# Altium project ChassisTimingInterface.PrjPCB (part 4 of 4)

## Sheet ChassisTimingInterface7.SchDoc: External Sync
size B; Author: M. Pirello; Organization: LIGO Laboratory; Address1: California Institute of Technology; Address2: Massachusetts Institute of Technology; Address3: National Science Foundation; Address4: Australia 2086; DocumentNumber: 8; SheetNumber: 8; SheetTotal: 12; Size: B
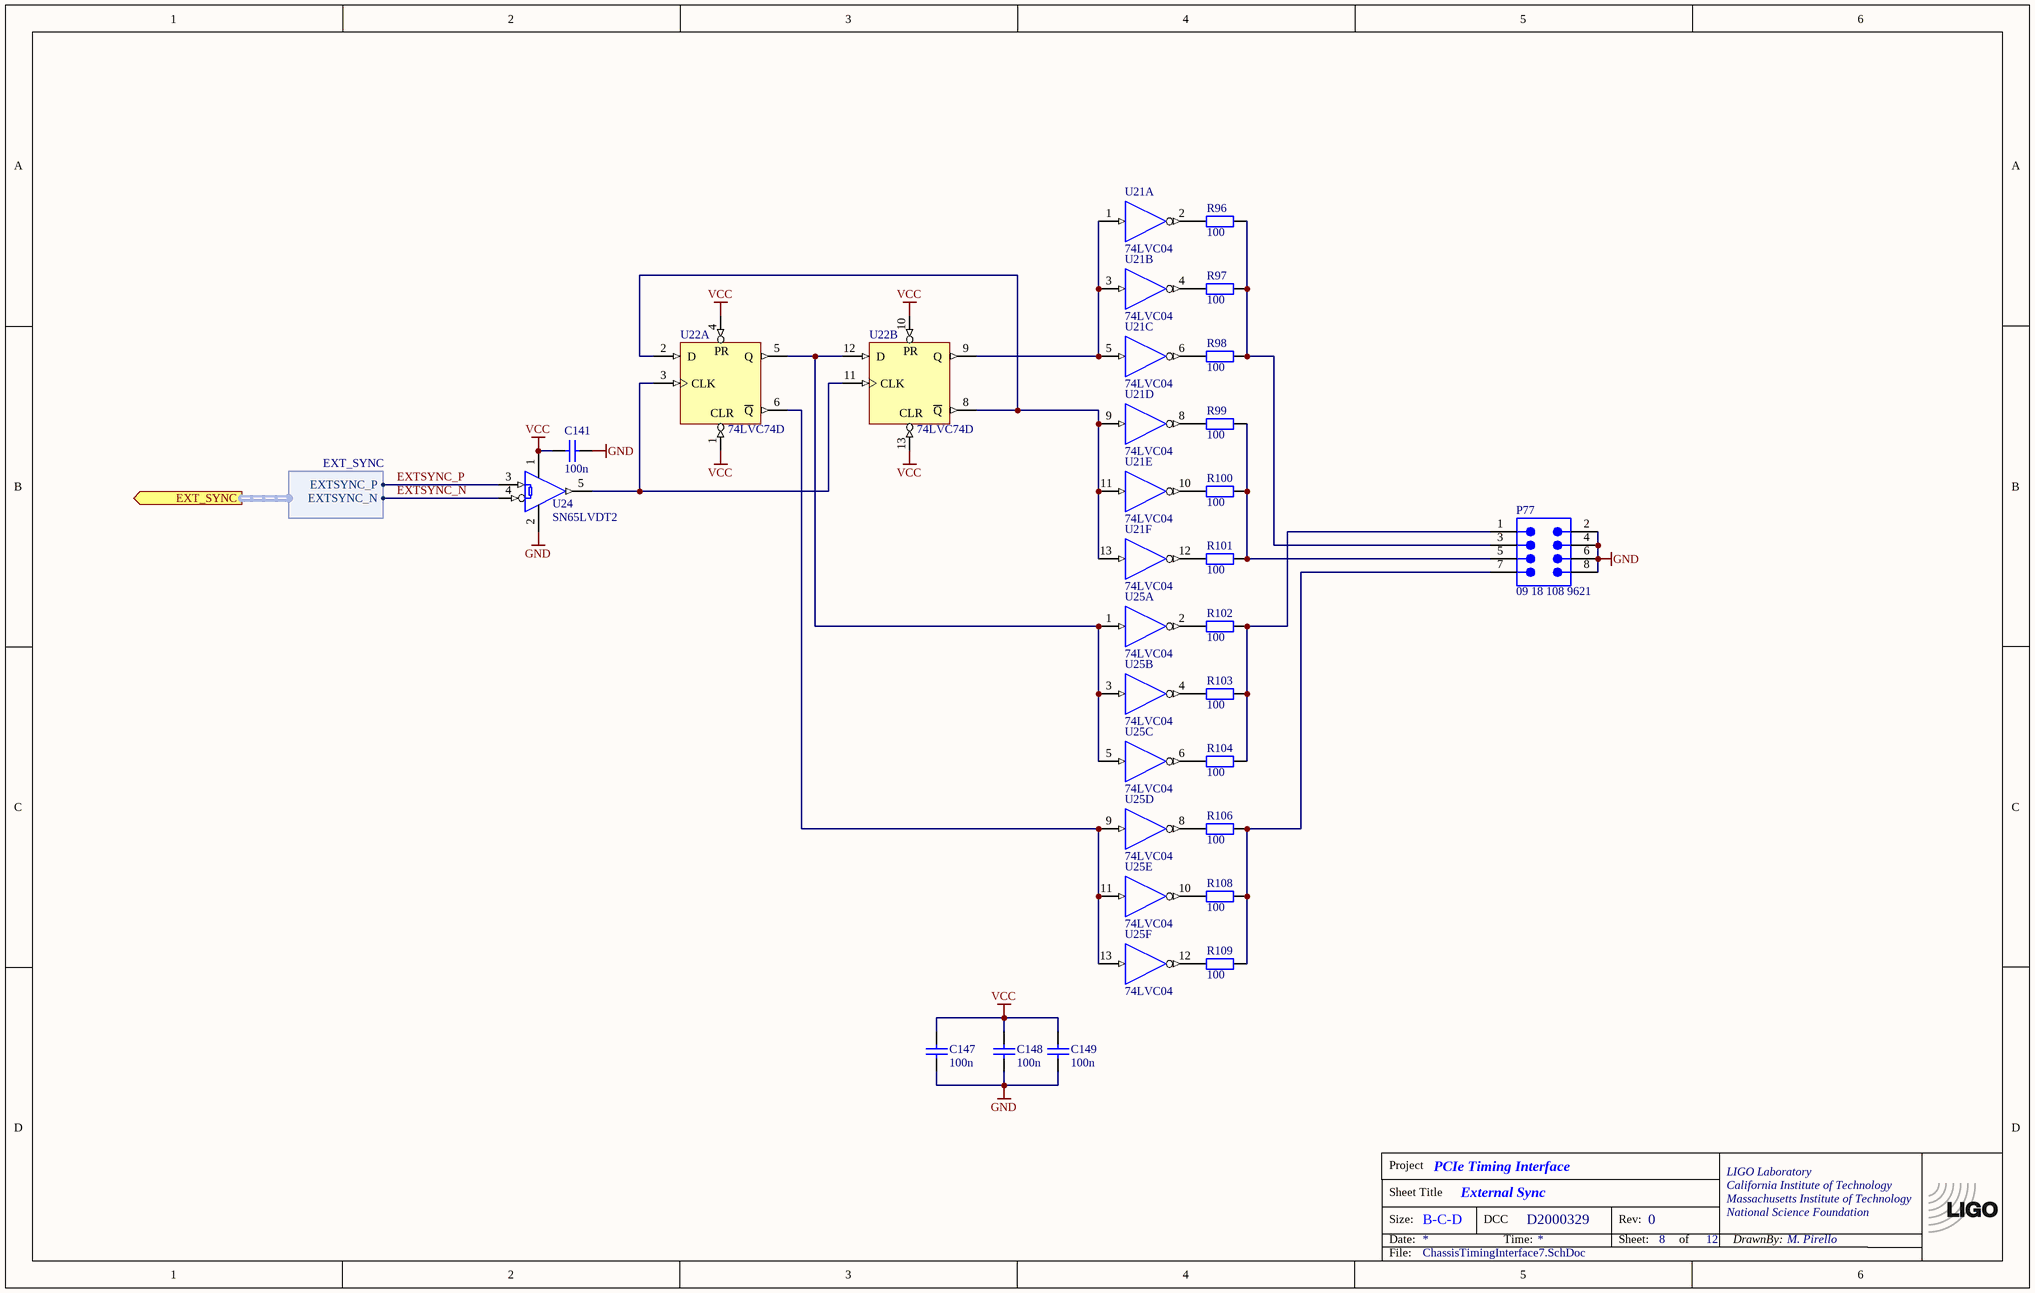
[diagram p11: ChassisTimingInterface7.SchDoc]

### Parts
(Parts that share a designator on the sheet are numbered #1, #2 ... from top to bottom, then left to right.)
*?#7  TitleBlock  (value not drawn)  (graphical)
?#2  (no value)  (no BOM)
C141  100n  [CC2013-0805]
C147  100n  [CC2013-0805]
C148  100n  [CC2013-0805]
C149  100n  [CC2013-0805]
P77  09 18 108 9621  [9181089621]
R96  100  [CR2012-0805]
R97  100  [CR2012-0805]
R98  100  [CR2012-0805]
R99  100  [CR2012-0805]
R100  100  [CR2012-0805]
R101  100  [CR2012-0805]
R102  100  [CR2012-0805]
R103  100  [CR2012-0805]
R104  100  [CR2012-0805]
R106  100  [CR2012-0805]
R108  100  [CR2012-0805]
R109  100  [CR2012-0805]
U21  74LVC04  [TSSOP14]  (parts A,B,C,D,E,F of 6)
U22  74LVC74D  [TSSOP14]  (parts A,B of 2)
U24  SN65LVDT2  [SO-G5/E2.4]
U25  74LVC04  [TSSOP14]  (parts A,B,C,D,E,F of 6)

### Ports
EXT_SYNC (out, harness EXT_SYNC)

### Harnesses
EXT_SYNC: EXTSYNC_N, EXTSYNC_P

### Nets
GND: C141.1 C147.2 C148.2 C149.2 P77.2 P77.4 P77.6 P77.8 U21.7(GND) U22.7(GND) U24.2(GND) U25.7(GND)
VCC: C141.2 C147.1 C148.1 C149.1 U21.14(VCC) U22.1(CLR) U22.4(PR) U22.10(PR) U22.13(CLR) U22.14(VCC) U24.1(VCC) U25.14(VCC)
EXTSYNC_N: U24.4(B) ; port EXT_SYNC.EXTSYNC_N  [project net EXT_SYNC.EXTSYNC_N]
EXTSYNC_P: U24.3(A) ; port EXT_SYNC.EXTSYNC_P  [project net EXT_SYNC.EXTSYNC_P]
NetP77_1: P77.1 R102.2 R103.2 R104.2
NetP77_3: P77.3 R96.2 R97.2 R98.2
NetP77_5: P77.5 R99.2 R100.2 R101.2
NetP77_7: P77.7 R106.2 R108.2 R109.2
NetR96_1: R96.1 U21.2(Y)
NetR97_1: R97.1 U21.4(Y)
NetR98_1: R98.1 U21.6(Y)
NetR99_1: R99.1 U21.8(Y)
NetR100_1: R100.1 U21.10(Y)
NetR101_1: R101.1 U21.12(Y)
NetR102_1: R102.1 U25.2(Y)
NetR103_1: R103.1 U25.4(Y)
NetR104_1: R104.1 U25.6(Y)
NetR106_1: R106.1 U25.8(Y)
NetR108_1: R108.1 U25.10(Y)
NetR109_1: R109.1 U25.12(Y)
NetU21_1: U21.1(A) U21.3(A) U21.5(A) U22.9(Q)
NetU21_9: U21.9(A) U21.11(A) U21.13(A) U22.2(D) U22.8(~{Q})
NetU22_3: U22.3(CLK) U22.11(CLK) U24.5(R)
NetU22_5: U22.5(Q) U22.12(D) U25.1(A) U25.3(A) U25.5(A)
NetU22_6: U22.6(~{Q}) U25.9(A) U25.11(A) U25.13(A)

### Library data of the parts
?#2 = LIGO_logo: LIGO logo
C141 C147-C149 = ChipCap: Capacitor, surface mount; Tolerance: 10%
P77 = 09 18 108 9621: Flat Cable Connector (IDC), PCB Transition Connector, 2 Rows, Solder Pin, 8 Contacts; PCB_Layout: Complies with manufacturer's recommendation.; DrillSize: Corresponds to nominal value.
R96-R104 R106 R108 R109 = ChipRes1: Resistor, surface mount; Part Number: RR12P100DCT-ND; Tolerance: 0.5%
U21 U25 = SN74AHCT04D: Hex Inverter; Part Number: 296-1218-1-ND
U22 = 74F74PC: Dual D-Type Positive Edge-Triggered Flip-Flop; Part Number: 296-1240-5-ND
U24 = SN65LVDT2DBV: Single LVDS Receiver with 100 Ohm termination

## Sheet ChassisTimingInterface_XADC.SchDoc: Power Supply
size B; DocumentNumber: 5; Revision: C; SheetNumber: 5; SheetTotal: 12
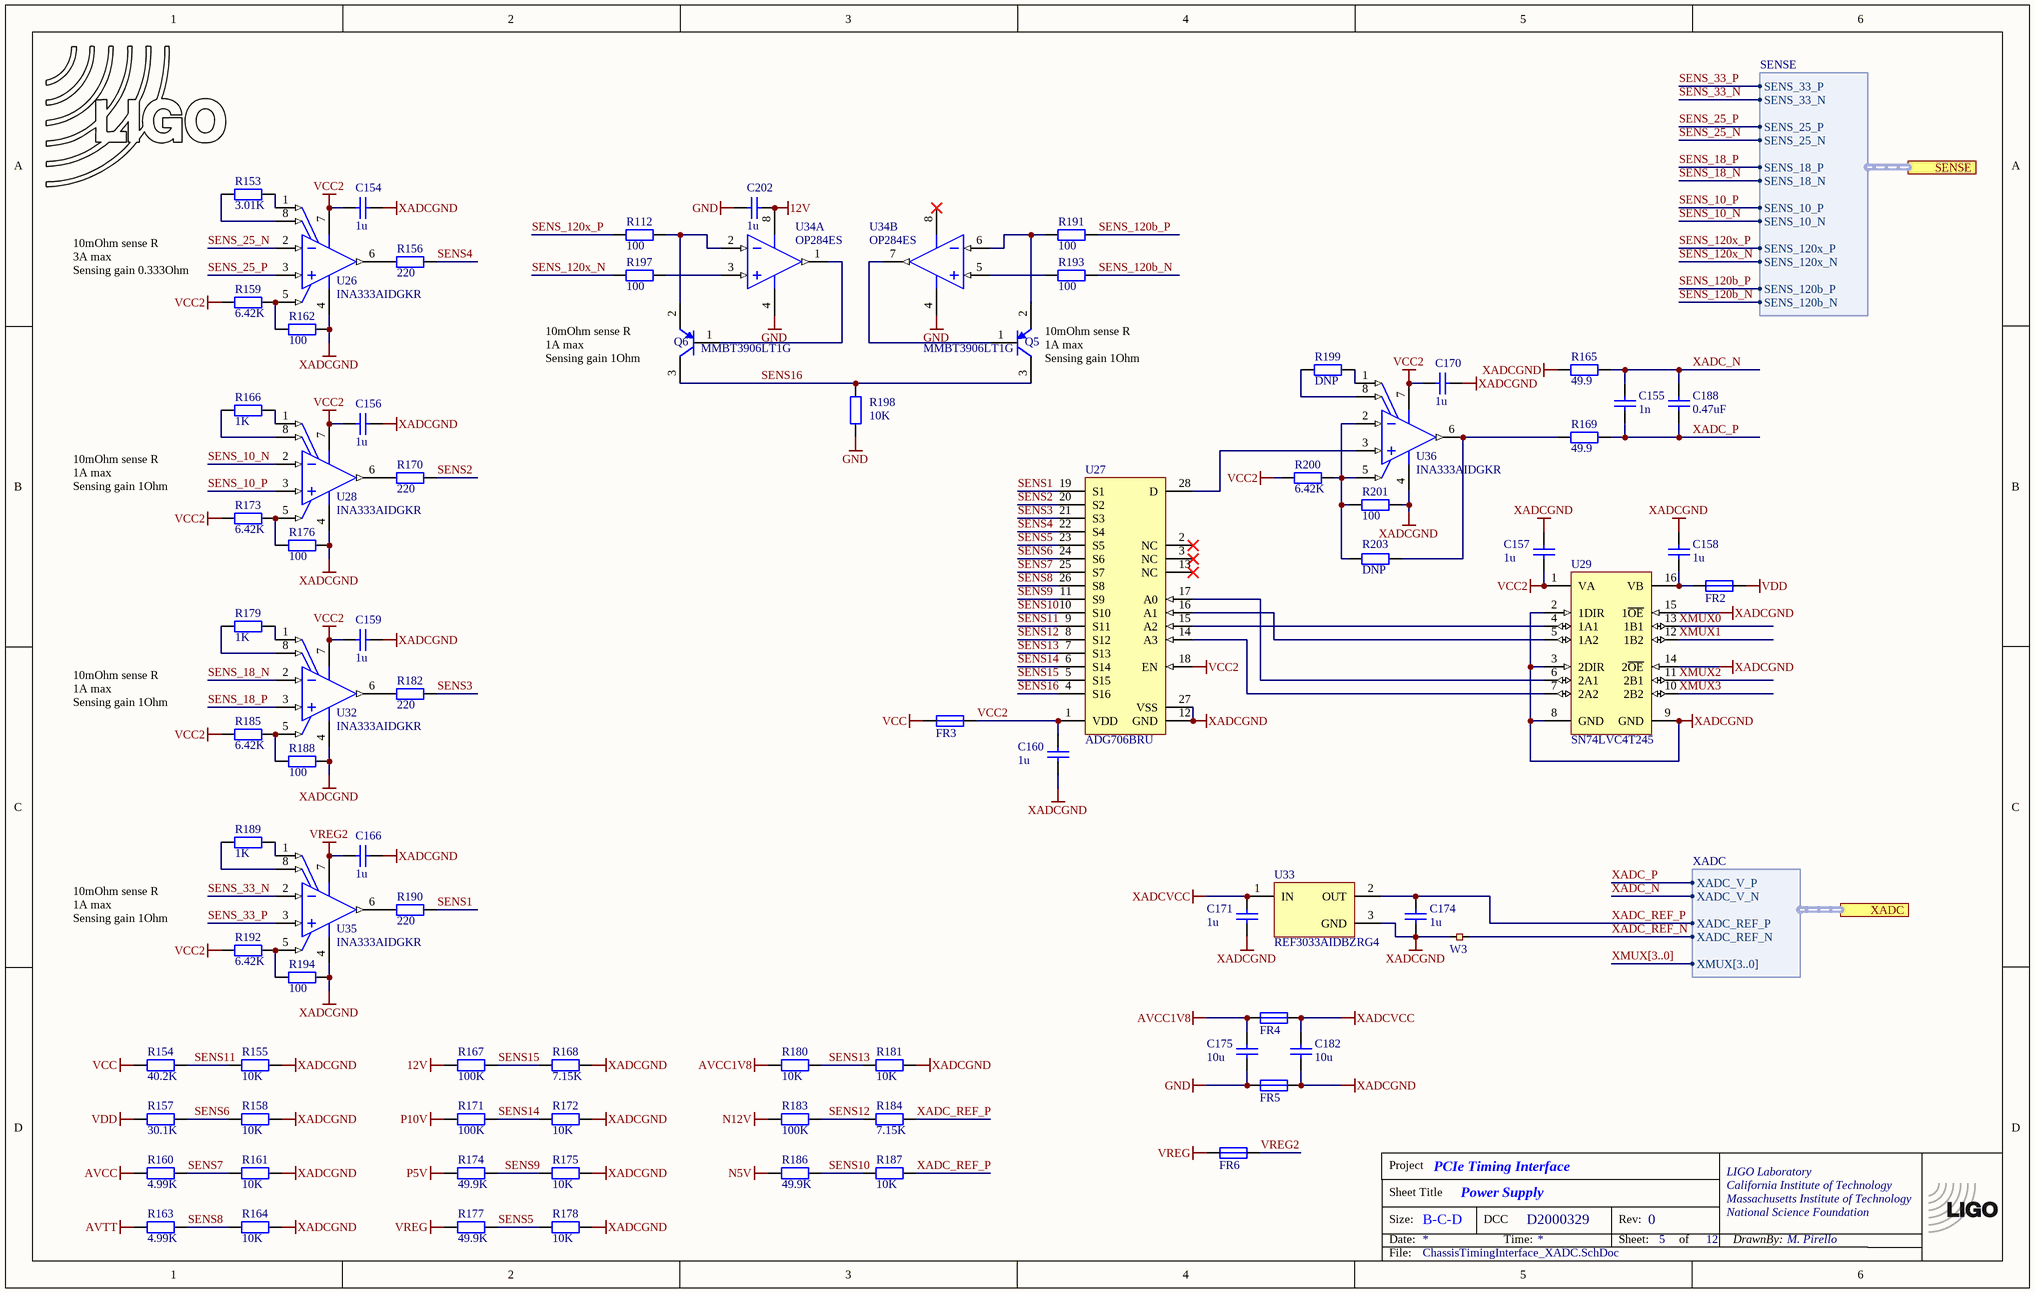
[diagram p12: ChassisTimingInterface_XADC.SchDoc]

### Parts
(Parts that share a designator on the sheet are numbered #1, #2 ... from top to bottom, then left to right.)
*#4  TitleBlock  (value not drawn)  (graphical)
C154  1u  [CC1608-0603]
C155  1n  [CC1608-0603]
C156  1u  [CC1608-0603]
C157  1u  [CC1608-0603]
C158  1u  [CC1608-0603]
C159  1u  [CC1608-0603]
C160  1u  [CC1608-0603]
C166  1u  [CC1608-0603]
C170  1u  [CC1608-0603]
C171  1u  [CC1608-0603]
C174  1u  [CC1608-0603]
C175  10u  [CC2013-0805]
C182  10u  [CC2013-0805]
C188  0.47uF  [CAPC0603X33X15NL03T05]
C202  1u  [CC1608-0603]
FR2  BLM31PG121  [CC3216-1206]  (value not drawn)
FR3  BLM31PG121  [CC3216-1206]  (value not drawn)
FR4  BLM31PG121  [CC3216-1206]  (value not drawn)
FR5  BLM31PG121  [CC3216-1206]  (value not drawn)
FR6  BLM31PG121  [CC3216-1206]  (value not drawn)
LOGO4#2  LIGO logo  [LIGO_LOGO]  (value not drawn)  (graphical)
Q5  MMBT3906LT1G  [ONSC-SOT-23-3-318-08_V]
Q6  MMBT3906LT1G  [ONSC-SOT-23-3-318-08_V]
R112  100  [CR2012-0805]
R153  3.01K  [CR1608-0603]
R154  40.2K  [CR1608-0603]
R155  10K  [CR1608-0603]
R156  220  [CR1608-0603]
R157  30.1K  [CR1608-0603]
R158  10K  [CR1608-0603]
R159  6.42K  [CR1608-0603]
R160  4.99K  [CR1608-0603]
R161  10K  [CR1608-0603]
R162  100  [CR1608-0603]
R163  4.99K  [CR1608-0603]
R164  10K  [CR1608-0603]
R165  49.9  [CR1608-0603]
R166  1K  [CR1608-0603]
R167  100K  [CR1608-0603]
R168  7.15K  [CR1608-0603]
R169  49.9  [CR1608-0603]
R170  220  [CR1608-0603]
R171  100K  [CR1608-0603]
R172  10K  [CR1608-0603]
R173  6.42K  [CR1608-0603]
R174  49.9K  [CR1608-0603]
R175  10K  [CR1608-0603]
R176  100  [CR1608-0603]
R177  49.9K  [CR1608-0603]
R178  10K  [CR1608-0603]
R179  1K  [CR1608-0603]
R180  10K  [CR1608-0603]
R181  10K  [CR1608-0603]
R182  220  [CR1608-0603]
R183  100K  [CR1608-0603]
R184  7.15K  [CR1608-0603]
R185  6.42K  [CR1608-0603]
R186  49.9K  [CR1608-0603]
R187  10K  [CR1608-0603]
R188  100  [CR1608-0603]
R189  1K  [CR1608-0603]
R190  220  [CR1608-0603]
R191  100  [CR2012-0805]
R192  6.42K  [CR1608-0603]
R193  100  [CR2012-0805]
R194  100  [CR1608-0603]
R197  100  [CR2012-0805]
R198  10K  [CR2012-0805]
R199  DNP  [CR1608-0603]
R200  6.42K  [CR1608-0603]
R201  100  [CR1608-0603]
R203  DNP  [CR1608-0603]
U26  INA333AIDGKR  [DGK0008A_N]
U27  ADG706BRU  [ADI-RU-28_M]
U28  INA333AIDGKR  [DGK0008A_N]
U29  SN74LVC4T245  [TSSOP16]
U32  INA333AIDGKR  [DGK0008A_N]
U33  REF3033AIDBZRG4  [TI-DBZ3_N]
U34  OP284ES  [ADI-R-8_N]  (parts A,B of 2)
U35  INA333AIDGKR  [DGK0008A_N]
U36  INA333AIDGKR  [DGK0008A_N]
W3  Net tie  [NETTIE1_SMDTOP]  (value not drawn)  (net tie, no BOM)

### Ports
SENSE (harness SENSE), XADC (harness XADC)

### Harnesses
XADC: XADC_REF_P, XADC_V_N, XADC_V_P, XMUX[3..0], XADC_REF_N
SENSE: SENS_33_P, SENS_33_N, SENS_25_P, SENS_25_N, SENS_18_P, SENS_18_N, SENS_10_P, SENS_10_N, SENS_120x_P, SENS_120x_N, SENS_120b_P, SENS_120b_N

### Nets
12V: C202.1 R167.1 R193.1 R197.2 U34.8(+V) ; port SENSE.SENS_120x_N, port SENSE.SENS_120b_N  [also labelled SENS_120b_N, SENS_120x_N]
AVCC: R160.1
AVCC1V8: C175.1 FR4.1 R180.1
AVTT: R163.1
GND: C175.2 C202.2 FR5.1 R198.1 U34.4(-V)
N5V: R186.1
N12V: R183.1
P5V: R174.1
P10V: R171.1
SENS_10_N: U28.2(VIN-) ; port SENSE.SENS_10_N  [project net VCCINT]
SENS_18_N: U32.2(VIN-) ; port SENSE.SENS_18_N  [project net VCC1V8]
VCC: FR3.1 R154.1 U35.2(VIN-) ; port SENSE.SENS_33_N  [also labelled SENS_33_N]
VCC2: C154.1 C156.1 C157.2 C159.1 C160.1 C170.1 FR3.2 R159.1 R173.1 R185.1 R192.1 R200.1 U26.7(V+) U27.1(VDD) U27.18(EN) U28.7(V+) U29.1(VA) U32.7(V+) U36.7(V+)
VDD: FR2.2 R157.1 U26.2(VIN-) ; port SENSE.SENS_25_N  [also labelled SENS_25_N]
VREG: FR6.1 R177.1
VREG2: C166.1 FR6.2 U35.7(V+)
XADCGND: C154.2 C156.2 C157.1 C158.1 C159.2 C160.2 C166.2 C170.2 C171.2 C174.2 C182.2 FR5.2 R155.2 R158.2 R161.2 R162.2 R164.2 R165.1 R168.2 R172.2 R175.2 R176.2 R178.2 R181.2 R188.2 R194.2 R201.2 U26.4(V-) U27.12(GND) U27.27(VSS) U28.4(V-) U29.2(1DIR) U29.3(2DIR) U29.8(GND) U29.9(GND) U29.14(2~{OE}) U29.15(1~{OE}) U32.4(V-) U33.3(GND) U35.4(V-) U36.4(V-) W3.1
XADCVCC: C171.1 C182.1 FR4.2 U33.1(IN)
SENS1: R190.2 U27.19(S1)
SENS2: R170.2 U27.20(S2)
SENS3: R182.2 U27.21(S3)
SENS4: R156.2 U27.22(S4)
SENS5: R177.2 R178.1 U27.23(S5)
SENS6: R157.2 R158.1 U27.24(S6)
SENS7: R160.2 R161.1 U27.25(S7)
SENS8: R163.2 R164.1 U27.26(S8)
SENS9: R174.2 R175.1 U27.11(S9)
SENS10: R186.2 R187.1 U27.10(S10)
SENS11: R154.2 R155.1 U27.9(S11)
SENS12: R183.2 R184.1 U27.8(S12)
SENS13: R180.2 R181.1 U27.7(S13)
SENS14: R171.2 R172.1 U27.6(S14)
SENS15: R167.2 R168.1 U27.5(S15)
SENS16: Q5.3(C) Q6.3(C) R198.2 U27.4(S16)
SENS_10_P: U28.3(VIN+) ; port SENSE.SENS_10_P  [project net SENSE.SENS_10_P]
SENS_18_P: U32.3(VIN+) ; port SENSE.SENS_18_P  [project net SENSE.SENS_18_P]
SENS_25_P: U26.3(VIN+) ; port SENSE.SENS_25_P  [project net SENSE.SENS_25_P]
SENS_33_P: U35.3(VIN+) ; port SENSE.SENS_33_P  [project net SENSE.SENS_33_P]
SENS_120b_P: R191.1 ; port SENSE.SENS_120b_P  [project net SENSE.SENS_120b_P]
SENS_120x_P: R112.2 ; port SENSE.SENS_120x_P  [project net SENSE.SENS_120x_P]
XADC_N: C155.2 C188.2 R165.2 ; port XADC.XADC_V_N  [project net XADC.XADC_V_N]
XADC_P: C155.1 C188.1 R169.2 ; port XADC.XADC_V_P  [project net XADC.XADC_V_P]
XADC_REF_N: W3.2 ; port XADC.XADC_REF_N  [project net XADC.XADC_REF_N]
XADC_REF_P: C174.1 R184.2 R187.2 U33.2(OUT) ; port XADC.XADC_REF_P  [project net XADC.XADC_REF_P]
XMUX0: U29.13(1B1)
XMUX1: U29.12(1B2)
XMUX2: U29.11(2B1)
XMUX3: U29.10(2B2)
NetC158_2: C158.2 FR2.1 U29.16(VB)
NetQ5_1: Q5.1(B) U34.7(OUT_B)
NetQ5_2: Q5.2(E) R191.2 U34.6(-IN_B)
NetQ6_1: Q6.1(B) U34.1(OUT_A)
NetQ6_2: Q6.2(E) R112.1 U34.2(-IN_A)
NetR153_1: R153.1 U26.8(RG)
NetR153_2: R153.2 U26.1(RG)
NetR156_1: R156.1 U26.6(VOUT)
NetR159_2: R159.2 R162.1 U26.5(REF)
NetR166_1: R166.1 U28.8(RG)
NetR166_2: R166.2 U28.1(RG)
NetR169_1: R169.1 R203.1 U36.6(VOUT)
NetR170_1: R170.1 U28.6(VOUT)
NetR173_2: R173.2 R176.1 U28.5(REF)
NetR179_1: R179.1 U32.8(RG)
NetR179_2: R179.2 U32.1(RG)
NetR182_1: R182.1 U32.6(VOUT)
NetR185_2: R185.2 R188.1 U32.5(REF)
NetR189_1: R189.1 U35.8(RG)
NetR189_2: R189.2 U35.1(RG)
NetR190_1: R190.1 U35.6(VOUT)
NetR192_2: R192.2 R194.1 U35.5(REF)
NetR193_2: R193.2 U34.5(+IN_B)
NetR197_1: R197.1 U34.3(+IN_A)
NetR199_1: R199.1 U36.8(RG)
NetR199_2: R199.2 U36.1(RG)
NetR200_2: R200.2 R201.1 R203.2 U36.2(VIN-) U36.5(REF)
NetU27_14: U27.14(A3) U29.7(2A2)
NetU27_15: U27.15(A2) U29.4(1A1)
NetU27_16: U27.16(A1) U29.5(1A2)
NetU27_17: U27.17(A0) U29.6(2A1)
NetU27_28: U27.28(D) U36.3(VIN+)

Not connected (* = marked no-connect by the designer): U27 2(NC)* 3(NC)* 13(NC)*

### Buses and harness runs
bus XMUX[3..0]

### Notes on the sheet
- 10mOhm sense R
  3A max
  Sensing gain 0.333Ohm
- (near Q6) 10mOhm sense R
  1A max
  Sensing gain 1Ohm
- (near Q5) 10mOhm sense R
  1A max
  Sensing gain 1Ohm
- 10mOhm sense R
  1A max
  Sensing gain 1Ohm

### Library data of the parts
C154-C160 C166 C170 C171 C174 C175 C182 = ChipCap: Capacitor, surface mount; Tolerance: 10%
C188 = CMP-2010-00306-1: Part Number: CL03A474MR3NNNC; Manufacturer: Samsung
C202 = ChipCap: Capacitor, surface mount; Part Number: PCC1893CT-ND; Tolerance: 10%; Voltage Rating: 25V
FR2-FR6 = BLM31PG121SN1: ferrite bead, 120Ohm at 100MHz, 1206
LOGO4#2 = LIGO_logo
Q5 Q6 = CMP-1048-00670-1: General Purpose Transistor, PNP Silicon, 3-Pin SOT-23, Pb-Free, Tape and Reel; Manufacturer: On Semiconductor; IC Continuous (A): -0.2; fT Min (MHz): 250
R112 R191 R193 R197 = Res2: Resistor; Part Number: RR12P1.0KBCT-ND; Tolerance: 0.1%
R153-R190 R192 R194 R199-R201 = ChipRes1: Resistor, surface mount; Tolerance: 1%
R198 R203 = Res2: Resistor; Part Number: RR12P26.1KBCT-ND; Tolerance: 0.1%
U26 U28 U32 U35 U36 = CMP-0944-00088-2: Low Power, Precision Instrumentation Amplifier, -40 to 125 degC, 8-pin SOP (DGK8), Green (RoHS & no Sb/Br); Manufacturer: Texas Instruments; Input Offset Drift (+/-)(Max)(uV/Degrees Celsius): 0.1; Vs(Max)(V): 5.5; Input Bias Current (+/-)(Max)(nA): 0.2; Output Offset (+/-)(Max)(uV): 75/G; CMRR(Min)(dB): 100; Noise at 1kHz(Typ)(nV/rt(Hz)): 50; Output Offset Drift (+/-)(Max)(uV/Degrees Celsius): 0.5/G; Vs(Min)(V): 1.8; Quiescent Current (+/-)(Typ)(mA): 0.05; Gain(V/V): 1 to 1000; SubFamily: Single Supply; Number of Channels: 1; Input Offset (+/-)(Max)(uV): 25
U27 = CMP-0798-00217-1: 1.8 to 5.5 V / 2.5 V, CMOS Low-Voltage 2.5 Ohm, 16-Channel Multiplexer, -40 to 85 degC, 28-pin SOP (RU-28), Tube; Manufacturer: Analog Devices; Ron (ohms): 2.5; Bandwidth (Hz): 25M; Supply V Guar Performance: Dual_(+/-2.5V), Single_(+3V), Single_(+5V); Max Analog Signal Range: Vss to Vdd; t transition (s): 40n
U29 = SN74LVC4T245: Quad-Bit Dual Supply Transceiver
U33 = CMP-0367-00169-1: 3.3 V, 50 ppm / degC, 50 uA Series (Bandgap) Voltage Reference, -40 to 125 degC, 3-pin SOT-23 (DBZ), Green (RoHS & no Sb/Br); Manufacturer: Texas Instruments; SubFamily: Series Voltage Reference; VI(Min)(V): 3.301; Iq(Max)(uA): 50; VI(Max)(V): 5.5; VO(V): 3.3; Initial Accuracy @ 25/deg C(%): 0.2; Rating: Catalog; Temp Coeff(Typ)(ppm/ degree C): 20
U34 = CMP-0384-00702-1: Double Channel Single-Supply Operation Operational Amplifier, 4.25 MHz BW, 4 V/us SR, Industrial, 8-pin SOIC (R-8), Tube; Generic Part Number: OP284; Manufacturer: Analog Devices; Input Offset Voltage: 175uV; Input Bias Current: 80nA; Iq/Amp: 2mA; Amplifiers Per Package: 2; V Span Min: 3V; Slew Rate: 4V/us; V Span Max: 36V
W3 = NetTie1_small: Tie two nets together

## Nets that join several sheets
12V: ChassisTimingInterface1 (P223.77 P223.79), ChassisTimingInterface2 (FL4.1), ChassisTimingInterface4 (13 pins), PCI Express_16765X11115_36PIN_Half length (R34.2), ChassisTimingInterface6 (5 pins), ChassisTimingInterface_XADC (5 pins)
AVCC: FPGA_ARTIX7 (5 pins), PCI Express_16765X11115_36PIN_Half length (7 pins), ChassisTimingInterface_XADC (R160.1)
AVCC1V8: ChassisTimingInterface4 (C196.2 R136.2 TP19.1 U31.7), ChassisTimingInterface_XADC (C175.1 FR4.1 R180.1)
AVTT: FPGA_ARTIX7 (7 pins), PCI Express_16765X11115_36PIN_Half length (7 pins), ChassisTimingInterface_XADC (R163.1)
GND: ChassisTimingInterface1 (38 pins), ChassisTimingInterface2 (15 pins), ChassisTimingInterface4 (61 pins), ChassisTimingInterface3 (21 pins), ChassisTimingInterface5 (72 pins), FPGA_ARTIX7 (94 pins), PCI Express_16765X11115_36PIN_Half length (31 pins), ChassisTimingInterface6 (20 pins), ChassisTimingInterface_SFP (25 pins), ChassisTimingInterface7 (12 pins), ChassisTimingInterface_XADC (5 pins)
N5V: ChassisTimingInterface6 (8 pins), ChassisTimingInterface_XADC (R186.1)
N12V: ChassisTimingInterface6 (6 pins), ChassisTimingInterface_XADC (R183.1)
P5V: ChassisTimingInterface6 (17 pins), ChassisTimingInterface_XADC (R174.1)
P10V: ChassisTimingInterface2 (10 pins), ChassisTimingInterface_XADC (R171.1)
VCC: ChassisTimingInterface1 (P223.1 P223.3 P223.5 P223.7), ChassisTimingInterface2 (15 pins), ChassisTimingInterface4 (R39.2 R133.2 R138.2 TP18.1), ChassisTimingInterface6 (8 pins), ChassisTimingInterface_SFP (12 pins), ChassisTimingInterface7 (12 pins), ChassisTimingInterface_XADC (FR3.1 R154.1 U35.2)
VCC1V8: ChassisTimingInterface4 (R130.2 R149.2 TP17.1), ChassisTimingInterface5 (9 pins), FPGA_ARTIX7 (5 pins), PCI Express_16765X11115_36PIN_Half length (L3.2 L8.2), ChassisTimingInterface_XADC (U32.2)
VCCINT: ChassisTimingInterface4 (R123.2 R143.2 TP16.1), ChassisTimingInterface5 (23 pins), FPGA_ARTIX7 (17 pins), ChassisTimingInterface_XADC (U28.2)
VDD: ChassisTimingInterface1 (P222.74 P222.76 P223.73 P223.75), ChassisTimingInterface2 (U7.10), ChassisTimingInterface4 (9 pins), ChassisTimingInterface3 (21 pins), ChassisTimingInterface5 (40 pins), FPGA_ARTIX7 (37 pins), PCI Express_16765X11115_36PIN_Half length (C150.1 U23.1), ChassisTimingInterface_SFP (R6.2 R151.2 R152.2), ChassisTimingInterface_XADC (FR2.2 R157.1 U26.2)
VREG: ChassisTimingInterface4 (7 pins), ChassisTimingInterface_XADC (FR6.1 R177.1)
XADCGND: ChassisTimingInterface5 (C134.1), FPGA_ARTIX7 (U18.K9), ChassisTimingInterface_XADC (42 pins)
XADCVCC: ChassisTimingInterface5 (C134.2), FPGA_ARTIX7 (U18.K10), ChassisTimingInterface_XADC (C171.1 C182.1 FR4.2 U33.1)
BACKPLANE.CLK0_N: ChassisTimingInterface1 (P199.21), FPGA_ARTIX7 (U18.C20)
BACKPLANE.CLK0_P: ChassisTimingInterface1 (P199.2), FPGA_ARTIX7 (U18.D20)
BACKPLANE.CLK1_N: ChassisTimingInterface1 (P199.30), FPGA_ARTIX7 (U18.B16)
BACKPLANE.CLK1_P: ChassisTimingInterface1 (P199.11), FPGA_ARTIX7 (U18.B15)
BACKPLANE.CLK2_N: ChassisTimingInterface1 (P199.29), FPGA_ARTIX7 (U18.C15)
BACKPLANE.CLK2_P: ChassisTimingInterface1 (P199.10), FPGA_ARTIX7 (U18.C14)
BACKPLANE.CLK3_N: ChassisTimingInterface1 (P199.28), FPGA_ARTIX7 (U18.A19)
BACKPLANE.CLK3_P: ChassisTimingInterface1 (P199.9), FPGA_ARTIX7 (U18.A18)
BACKPLANE.CLK4_N: ChassisTimingInterface1 (P199.27), FPGA_ARTIX7 (U18.D15)
BACKPLANE.CLK4_P: ChassisTimingInterface1 (P199.8), FPGA_ARTIX7 (U18.D14)
BACKPLANE.CLK5_N: ChassisTimingInterface1 (P199.26), FPGA_ARTIX7 (U18.A20)
BACKPLANE.CLK5_P: ChassisTimingInterface1 (P199.7), FPGA_ARTIX7 (U18.B20)
BACKPLANE.CLK6_N: ChassisTimingInterface1 (P199.25), FPGA_ARTIX7 (U18.D16)
BACKPLANE.CLK6_P: ChassisTimingInterface1 (P199.6), FPGA_ARTIX7 (U18.E16)
BACKPLANE.CLK7_N: ChassisTimingInterface1 (P199.24), FPGA_ARTIX7 (U18.A21)
BACKPLANE.CLK7_P: ChassisTimingInterface1 (P199.5), FPGA_ARTIX7 (U18.B21)
BACKPLANE.CLK8_N: ChassisTimingInterface1 (P199.23), FPGA_ARTIX7 (U18.C19)
BACKPLANE.CLK8_P: ChassisTimingInterface1 (P199.4), FPGA_ARTIX7 (U18.C18)
BACKPLANE.CLK9_N: ChassisTimingInterface1 (P199.22), FPGA_ARTIX7 (U18.B22)
BACKPLANE.CLK9_P: ChassisTimingInterface1 (P199.3), FPGA_ARTIX7 (U18.C22)
BACKPLANE.CS_N: ChassisTimingInterface1 (P199.32), FPGA_ARTIX7 (U18.B13)
BACKPLANE.CS_P: ChassisTimingInterface1 (P199.13), FPGA_ARTIX7 (U18.C13)
BACKPLANE.DIN_N: ChassisTimingInterface1 (P199.35), FPGA_ARTIX7 (U18.A14)
BACKPLANE.DIN_P: ChassisTimingInterface1 (P199.16), FPGA_ARTIX7 (U18.A13)
BACKPLANE.DOUT_N: ChassisTimingInterface1 (P199.34), FPGA_ARTIX7 (U18.G13)
BACKPLANE.DOUT_P: ChassisTimingInterface1 (P199.15), FPGA_ARTIX7 (U18.H13)
BACKPLANE.SCLK_N: ChassisTimingInterface1 (P199.33), FPGA_ARTIX7 (U18.A16)
BACKPLANE.SCLK_P: ChassisTimingInterface1 (P199.14), FPGA_ARTIX7 (U18.A15)
BACKPLANE.X1_N: ChassisTimingInterface1 (R95.1), FPGA_ARTIX7 (U18.E14)
BACKPLANE.X1_P: ChassisTimingInterface1 (R94.1), FPGA_ARTIX7 (U18.E13)
BACKPLANE.X3_N: ChassisTimingInterface1 (P199.31), FPGA_ARTIX7 (U18.B18)
BACKPLANE.X3_P: ChassisTimingInterface1 (P199.12), FPGA_ARTIX7 (U18.B17)
BACKPLANE.X5_N: ChassisTimingInterface1 (P199.20), FPGA_ARTIX7 (U18.D21)
BACKPLANE.X5_P: ChassisTimingInterface1 (P199.1), FPGA_ARTIX7 (U18.E21)
CFG_CLK: ChassisTimingInterface1 (P222.79), FPGA_ARTIX7 (U18.AA3)
CFG_CS: ChassisTimingInterface1 (P222.80), FPGA_ARTIX7 (U18.AB1)
CFG_SI: ChassisTimingInterface1 (P222.77), FPGA_ARTIX7 (U18.Y3)
CFG_SO: ChassisTimingInterface1 (P222.78), FPGA_ARTIX7 (U18.AA1)
CLOCK.ACLK_N: ChassisTimingInterface2 (U6.6), FPGA_ARTIX7 (U18.AB22)
CLOCK.ACLK_P: ChassisTimingInterface2 (U6.5), FPGA_ARTIX7 (U18.AB21)
CLOCK.ACNV_N: ChassisTimingInterface2 (U6.8), FPGA_ARTIX7 (U18.AA21)
CLOCK.ACNV_P: ChassisTimingInterface2 (U6.7), FPGA_ARTIX7 (U18.AA20)
CLOCK.AIN_N: ChassisTimingInterface2 (U6.10), FPGA_ARTIX7 (U18.Y22)
CLOCK.AIN_P: ChassisTimingInterface2 (U6.9), FPGA_ARTIX7 (U18.Y21)
CLOCK.CNTROUT_N: ChassisTimingInterface2 (U6.4), FPGA_ARTIX7 (U18.AB20)
CLOCK.CNTROUT_P: ChassisTimingInterface2 (U6.3), FPGA_ARTIX7 (U18.AA19)
CLOCK.OSCCLK_N: ChassisTimingInterface2 (U10.4), FPGA_ARTIX7 (U18.Y19)
CLOCK.OSCCLK_P: ChassisTimingInterface2 (U10.5), FPGA_ARTIX7 (U18.Y18)
CLOCK.SYNC_N: ChassisTimingInterface2 (U6.2), FPGA_ARTIX7 (U18.AB18)
CLOCK.SYNC_P: ChassisTimingInterface2 (U6.1), FPGA_ARTIX7 (U18.AA18)
DAC_REF.DOUT0_N: FPGA_ARTIX7 (U18.B2), ChassisTimingInterface6 (U46.6)
DAC_REF.DOUT0_P: FPGA_ARTIX7 (U18.C2), ChassisTimingInterface6 (U46.5)
DAC_REF.DOUT1_N: FPGA_ARTIX7 (U18.A1), ChassisTimingInterface6 (U46.8)
DAC_REF.DOUT1_P: FPGA_ARTIX7 (U18.B1), ChassisTimingInterface6 (U46.7)
DAC_REF.DSCLK_N: FPGA_ARTIX7 (U18.D1), ChassisTimingInterface6 (U46.2)
DAC_REF.DSCLK_P: FPGA_ARTIX7 (U18.E1), ChassisTimingInterface6 (U46.1)
DAC_REF.DSYNC_N: FPGA_ARTIX7 (U18.D2), ChassisTimingInterface6 (U46.4)
DAC_REF.DSYNC_P: FPGA_ARTIX7 (U18.E2), ChassisTimingInterface6 (U46.3)
DAC_REF.INVSYNC_N: FPGA_ARTIX7 (U18.W5), ChassisTimingInterface6 (U30.4)
DAC_REF.INVSYNC_P: FPGA_ARTIX7 (U18.W6), ChassisTimingInterface6 (U30.3)
DAC_REF.REFCLK_N: FPGA_ARTIX7 (U18.W20), ChassisTimingInterface6 (U17.6)
DAC_REF.REFCLK_P: FPGA_ARTIX7 (U18.W19), ChassisTimingInterface6 (U17.7)
DUOTONE_N: ChassisTimingInterface1 (P199.36), ChassisTimingInterface6 (R67.2)
DUOTONE_P: ChassisTimingInterface1 (P199.17), ChassisTimingInterface6 (R65.2)
EXT_SYNC.EXTSYNC_N: FPGA_ARTIX7 (U18.L13), ChassisTimingInterface7 (U24.4)
EXT_SYNC.EXTSYNC_P: FPGA_ARTIX7 (U18.M13), ChassisTimingInterface7 (U24.3)
PCIE.PCIE_CLK_N: FPGA_ARTIX7 (U18.E6), PCI Express_16765X11115_36PIN_Half length (C83.2)
PCIE.PCIE_CLK_P: FPGA_ARTIX7 (U18.F6), PCI Express_16765X11115_36PIN_Half length (C82.2)
PCIE.PCIE_PERST: FPGA_ARTIX7 (U18.F4), PCI Express_16765X11115_36PIN_Half length (U23.3)
PCIE.PCIE_PWRGD: FPGA_ARTIX7 (U18.T3), PCI Express_16765X11115_36PIN_Half length (R85.1 U20.5)
PCIE.PCIE_TX0_N: FPGA_ARTIX7 (U18.A4), PCI Express_16765X11115_36PIN_Half length (C84.2)
PCIE.PCIE_TX0_P: FPGA_ARTIX7 (U18.B4), PCI Express_16765X11115_36PIN_Half length (C86.2)
POWER.PWRGOOD: ChassisTimingInterface4 (R31.1 U31.20), FPGA_ARTIX7 (U18.AB5)
POWER.PWRINT: ChassisTimingInterface4 (R41.1), FPGA_ARTIX7 (U18.AA5)
POWER.PWRSCL: ChassisTimingInterface4 (R45.1), FPGA_ARTIX7 (U18.AA6)
POWER.PWRSDA: ChassisTimingInterface4 (R43.1), FPGA_ARTIX7 (U18.Y6)
POWER.PWRSYNC_N: ChassisTimingInterface4 (U15.4), FPGA_ARTIX7 (U18.AB2)
POWER.PWRSYNC_P: ChassisTimingInterface4 (U15.3), FPGA_ARTIX7 (U18.AB3)
S1_16.S1_N: ChassisTimingInterface1 (P222.12), FPGA_ARTIX7 (U18.G4)
S1_16.S1_P: ChassisTimingInterface1 (P222.10), FPGA_ARTIX7 (U18.H4)
S1_16.S2_N: ChassisTimingInterface1 (P222.14), FPGA_ARTIX7 (U18.F1)
S1_16.S2_P: ChassisTimingInterface1 (P222.16), FPGA_ARTIX7 (U18.G1)
S1_16.S3_N: ChassisTimingInterface1 (P222.20), FPGA_ARTIX7 (U18.J6)
S1_16.S3_P: ChassisTimingInterface1 (P222.18), FPGA_ARTIX7 (U18.K6)
S1_16.S4_N: ChassisTimingInterface1 (P222.22), FPGA_ARTIX7 (U18.J1)
S1_16.S4_P: ChassisTimingInterface1 (P222.24), FPGA_ARTIX7 (U18.K1)
S1_16.S5_N: ChassisTimingInterface1 (P222.28), FPGA_ARTIX7 (U18.M5)
S1_16.S5_P: ChassisTimingInterface1 (P222.26), FPGA_ARTIX7 (U18.M6)
S1_16.S6_N: ChassisTimingInterface1 (P222.30), FPGA_ARTIX7 (U18.L1)
S1_16.S6_P: ChassisTimingInterface1 (P222.32), FPGA_ARTIX7 (U18.M1)
S1_16.S7_N: ChassisTimingInterface1 (P222.36), FPGA_ARTIX7 (U18.R2)
S1_16.S7_P: ChassisTimingInterface1 (P222.34), FPGA_ARTIX7 (U18.R3)
S1_16.S8_N: ChassisTimingInterface1 (P222.38), FPGA_ARTIX7 (U18.J4)
S1_16.S8_P: ChassisTimingInterface1 (P222.40), FPGA_ARTIX7 (U18.K4)
S1_16.S9_N: ChassisTimingInterface1 (P222.44), FPGA_ARTIX7 (U18.T4)
S1_16.S9_P: ChassisTimingInterface1 (P222.42), FPGA_ARTIX7 (U18.R4)
S10_N: ChassisTimingInterface1 (P222.46), FPGA_ARTIX7 (U18.P1)
S10_P: ChassisTimingInterface1 (P222.48), FPGA_ARTIX7 (U18.R1)
S11_N: ChassisTimingInterface1 (P222.52), FPGA_ARTIX7 (U18.U1)
S11_P: ChassisTimingInterface1 (P222.50), FPGA_ARTIX7 (U18.T1)
S12_N: ChassisTimingInterface1 (P222.54), FPGA_ARTIX7 (U18.N5)
S12_P: ChassisTimingInterface1 (P222.56), FPGA_ARTIX7 (U18.P6)
S13_N: ChassisTimingInterface1 (P222.60), FPGA_ARTIX7 (U18.V2)
S13_P: ChassisTimingInterface1 (P222.58), FPGA_ARTIX7 (U18.U2)
S14_N: ChassisTimingInterface1 (P222.62), FPGA_ARTIX7 (U18.H15)
S14_P: ChassisTimingInterface1 (P222.64), FPGA_ARTIX7 (U18.J15)
S15_N: ChassisTimingInterface1 (P222.68), FPGA_ARTIX7 (U18.Y1)
S15_P: ChassisTimingInterface1 (P222.66), FPGA_ARTIX7 (U18.W1)
S16_N: ChassisTimingInterface1 (P222.70), FPGA_ARTIX7 (U18.W4)
S16_P: ChassisTimingInterface1 (P222.72), FPGA_ARTIX7 (U18.V4)
S17_32.S17_N: ChassisTimingInterface1 (P222.11), FPGA_ARTIX7 (U18.G3)
S17_32.S17_P: ChassisTimingInterface1 (P222.9), FPGA_ARTIX7 (U18.H3)
S17_32.S18_N: ChassisTimingInterface1 (P222.13), FPGA_ARTIX7 (U18.E3)
S17_32.S18_P: ChassisTimingInterface1 (P222.15), FPGA_ARTIX7 (U18.F3)
S17_32.S19_N: ChassisTimingInterface1 (P222.19), FPGA_ARTIX7 (U18.G2)
S17_32.S19_P: ChassisTimingInterface1 (P222.17), FPGA_ARTIX7 (U18.H2)
S17_32.S20_N: ChassisTimingInterface1 (P222.21), FPGA_ARTIX7 (U18.H5)
S17_32.S20_P: ChassisTimingInterface1 (P222.23), FPGA_ARTIX7 (U18.J5)
S17_32.S21_N: ChassisTimingInterface1 (P222.27), FPGA_ARTIX7 (U18.L4)
S17_32.S21_P: ChassisTimingInterface1 (P222.25), FPGA_ARTIX7 (U18.L5)
S17_32.S22_N: ChassisTimingInterface1 (P222.29), FPGA_ARTIX7 (U18.N3)
S17_32.S22_P: ChassisTimingInterface1 (P222.31), FPGA_ARTIX7 (U18.N4)
S17_32.S23_N: ChassisTimingInterface1 (P222.35), FPGA_ARTIX7 (U18.M2)
S17_32.S23_P: ChassisTimingInterface1 (P222.33), FPGA_ARTIX7 (U18.M3)
S17_32.S24_N: ChassisTimingInterface1 (P222.37), FPGA_ARTIX7 (U18.K3)
S17_32.S24_P: ChassisTimingInterface1 (P222.39), FPGA_ARTIX7 (U18.L3)
S17_32.S25_N: ChassisTimingInterface1 (P222.43), FPGA_ARTIX7 (U18.U5)
S17_32.S25_P: ChassisTimingInterface1 (P222.41), FPGA_ARTIX7 (U18.T5)
S17_32.S26_N: ChassisTimingInterface1 (P222.45), FPGA_ARTIX7 (U18.N2)
S17_32.S26_P: ChassisTimingInterface1 (P222.47), FPGA_ARTIX7 (U18.P2)
S17_32.S27_N: ChassisTimingInterface1 (P222.51), FPGA_ARTIX7 (U18.V3)
S17_32.S27_P: ChassisTimingInterface1 (P222.49), FPGA_ARTIX7 (U18.U3)
S17_32.S28_N: ChassisTimingInterface1 (P222.53), FPGA_ARTIX7 (U18.P4)
S17_32.S28_P: ChassisTimingInterface1 (P222.55), FPGA_ARTIX7 (U18.P5)
S17_32.S29_N: ChassisTimingInterface1 (P222.59), FPGA_ARTIX7 (U18.V5)
S17_32.S29_P: ChassisTimingInterface1 (P222.57), FPGA_ARTIX7 (U18.U6)
S17_32.S30_N: ChassisTimingInterface1 (P222.61), FPGA_ARTIX7 (U18.T6)
S17_32.S30_P: ChassisTimingInterface1 (P222.63), FPGA_ARTIX7 (U18.R6)
S17_32.S31_N: ChassisTimingInterface1 (P222.67), FPGA_ARTIX7 (U18.Y2)
S17_32.S31_P: ChassisTimingInterface1 (P222.65), FPGA_ARTIX7 (U18.W2)
S17_32.S32_N: ChassisTimingInterface1 (P222.69), FPGA_ARTIX7 (U18.AA4)
S17_32.S32_P: ChassisTimingInterface1 (P222.71), FPGA_ARTIX7 (U18.Y4)
S33_48.S33_N: ChassisTimingInterface1 (P223.11), FPGA_ARTIX7 (U18.F20)
S33_48.S33_P: ChassisTimingInterface1 (P223.9), FPGA_ARTIX7 (U18.F19)
S33_48.S34_N: ChassisTimingInterface1 (P223.13), FPGA_ARTIX7 (U18.D22)
S33_48.S34_P: ChassisTimingInterface1 (P223.15), FPGA_ARTIX7 (U18.E22)
S33_48.S35_N: ChassisTimingInterface1 (P223.19), FPGA_ARTIX7 (U18.G22)
S33_48.S35_P: ChassisTimingInterface1 (P223.17), FPGA_ARTIX7 (U18.G21)
S33_48.S36_N: ChassisTimingInterface1 (P223.21), FPGA_ARTIX7 (U18.H22)
S33_48.S36_P: ChassisTimingInterface1 (P223.23), FPGA_ARTIX7 (U18.J22)
S33_48.S37_N: ChassisTimingInterface1 (P223.27), FPGA_ARTIX7 (U18.E18)
S33_48.S37_P: ChassisTimingInterface1 (P223.25), FPGA_ARTIX7 (U18.F18)
S33_48.S38_N: ChassisTimingInterface1 (P223.29), FPGA_ARTIX7 (U18.G20)
S33_48.S38_P: ChassisTimingInterface1 (P223.31), FPGA_ARTIX7 (U18.H20)
S33_48.S39_N: ChassisTimingInterface1 (P223.35), FPGA_ARTIX7 (U18.J17)
S33_48.S39_P: ChassisTimingInterface1 (P223.33), FPGA_ARTIX7 (U18.K17)
S33_48.S40_N: ChassisTimingInterface1 (P223.37), FPGA_ARTIX7 (U18.C17)
S33_48.S40_P: ChassisTimingInterface1 (P223.39), FPGA_ARTIX7 (U18.D17)
S33_48.S41_N: ChassisTimingInterface1 (P223.43), FPGA_ARTIX7 (U18.K19)
S33_48.S41_P: ChassisTimingInterface1 (P223.41), FPGA_ARTIX7 (U18.K18)
S33_48.S42_N: ChassisTimingInterface1 (P223.45), FPGA_ARTIX7 (U18.K16)
S33_48.S42_P: ChassisTimingInterface1 (P223.47), FPGA_ARTIX7 (U18.L16)
S33_48.S43_N: ChassisTimingInterface1 (P223.51), FPGA_ARTIX7 (U18.K22)
S33_48.S43_P: ChassisTimingInterface1 (P223.49), FPGA_ARTIX7 (U18.K21)
S33_48.S44_N: ChassisTimingInterface1 (P223.53), FPGA_ARTIX7 (U18.L21)
S33_48.S44_P: ChassisTimingInterface1 (P223.55), FPGA_ARTIX7 (U18.M21)
S33_48.S45_N: ChassisTimingInterface1 (P223.59), FPGA_ARTIX7 (U18.R19)
S33_48.S45_P: ChassisTimingInterface1 (P223.57), FPGA_ARTIX7 (U18.P19)
S33_48.S46_N: ChassisTimingInterface1 (P223.61), FPGA_ARTIX7 (U18.M22)
S33_48.S46_P: ChassisTimingInterface1 (P223.63), FPGA_ARTIX7 (U18.N22)
S33_48.S47_N: ChassisTimingInterface1 (P223.67), FPGA_ARTIX7 (U18.U18)
S33_48.S47_P: ChassisTimingInterface1 (P223.65), FPGA_ARTIX7 (U18.U17)
S33_48.S48_N: ChassisTimingInterface1 (P223.69), FPGA_ARTIX7 (U18.H19)
S33_48.S48_P: ChassisTimingInterface1 (P223.71), FPGA_ARTIX7 (U18.J19)
S49_64.S49_N: ChassisTimingInterface1 (P223.12), FPGA_ARTIX7 (U18.D19)
S49_64.S49_P: ChassisTimingInterface1 (P223.10), FPGA_ARTIX7 (U18.E19)
S49_64.S50_N: ChassisTimingInterface1 (P223.14), FPGA_ARTIX7 (U18.F14)
S49_64.S50_P: ChassisTimingInterface1 (P223.16), FPGA_ARTIX7 (U18.F13)
S49_64.S51_N: ChassisTimingInterface1 (P223.20), FPGA_ARTIX7 (U18.G16)
S49_64.S51_P: ChassisTimingInterface1 (P223.18), FPGA_ARTIX7 (U18.G15)
S49_64.S52_N: ChassisTimingInterface1 (P223.22), FPGA_ARTIX7 (U18.H14)
S49_64.S52_P: ChassisTimingInterface1 (P223.24), FPGA_ARTIX7 (U18.J14)
S49_64.S53_N: ChassisTimingInterface1 (P223.28), FPGA_ARTIX7 (U18.G18)
S49_64.S53_P: ChassisTimingInterface1 (P223.26), FPGA_ARTIX7 (U18.G17)
S49_64.S54_N: ChassisTimingInterface1 (P223.30), FPGA_ARTIX7 (U18.H18)
S49_64.S54_P: ChassisTimingInterface1 (P223.32), FPGA_ARTIX7 (U18.H17)
S49_64.S55_N: ChassisTimingInterface1 (P223.36), FPGA_ARTIX7 (U18.K14)
S49_64.S55_P: ChassisTimingInterface1 (P223.34), FPGA_ARTIX7 (U18.K13)
S49_64.S56_N: ChassisTimingInterface1 (P223.38), FPGA_ARTIX7 (U18.J21)
S49_64.S56_P: ChassisTimingInterface1 (P223.40), FPGA_ARTIX7 (U18.J20)
S49_64.S57_N: ChassisTimingInterface1 (P223.44), FPGA_ARTIX7 (U18.L20)
S49_64.S57_P: ChassisTimingInterface1 (P223.42), FPGA_ARTIX7 (U18.L19)
S49_64.S58_N: ChassisTimingInterface1 (P223.46), FPGA_ARTIX7 (U18.E17)
S49_64.S58_P: ChassisTimingInterface1 (P223.48), FPGA_ARTIX7 (U18.F16)
S49_64.S59_N: ChassisTimingInterface1 (P223.52), FPGA_ARTIX7 (U18.M16)
S49_64.S59_P: ChassisTimingInterface1 (P223.50), FPGA_ARTIX7 (U18.M15)
S49_64.S60_N: ChassisTimingInterface1 (P223.54), FPGA_ARTIX7 (U18.M20)
S49_64.S60_P: ChassisTimingInterface1 (P223.56), FPGA_ARTIX7 (U18.N20)
S49_64.S61_N: ChassisTimingInterface1 (P223.60), FPGA_ARTIX7 (U18.P17)
S49_64.S61_P: ChassisTimingInterface1 (P223.58), FPGA_ARTIX7 (U18.N17)
S49_64.S62_N: ChassisTimingInterface1 (P223.62), FPGA_ARTIX7 (U18.T18)
S49_64.S62_P: ChassisTimingInterface1 (P223.64), FPGA_ARTIX7 (U18.R18)
S49_64.S63_N: ChassisTimingInterface1 (P223.68), FPGA_ARTIX7 (U18.U21)
S49_64.S63_P: ChassisTimingInterface1 (P223.66), FPGA_ARTIX7 (U18.T21)
S49_64.S64_N: ChassisTimingInterface1 (P223.70), FPGA_ARTIX7 (U18.V19)
S49_64.S64_P: ChassisTimingInterface1 (P223.72), FPGA_ARTIX7 (U18.V18)
SENSE.SENS_10_P: ChassisTimingInterface4 (C187.1 L6.2 R123.1 R124.2), ChassisTimingInterface_XADC (U28.3)
SENSE.SENS_18_P: ChassisTimingInterface4 (C193.2 L7.2 R130.1 R131.2), ChassisTimingInterface_XADC (U32.3)
SENSE.SENS_25_P: ChassisTimingInterface4 (C186.2 L4.2 R38.2 R120.1), ChassisTimingInterface_XADC (U26.3)
SENSE.SENS_33_P: ChassisTimingInterface4 (C195.2 L10.2 R133.1 R134.2), ChassisTimingInterface_XADC (U35.3)
SENSE.SENS_120b_P: PCI Express_16765X11115_36PIN_Half length (D1.2 R34.1), ChassisTimingInterface_XADC (R191.1)
SENSE.SENS_120x_P: ChassisTimingInterface4 (C48.1 D2.2 R196.1), ChassisTimingInterface_XADC (R112.2)
SFPIN.LEDIN: FPGA_ARTIX7 (U18.V17), ChassisTimingInterface_SFP (Q1.1)
SFPIN.LOS: FPGA_ARTIX7 (U18.W17), ChassisTimingInterface_SFP (J1.8 R152.1)
SFPIN.SYNCIN_N: FPGA_ARTIX7 (U18.R17), ChassisTimingInterface_SFP (U4.7)
SFPIN.SYNCIN_P: FPGA_ARTIX7 (U18.P16), ChassisTimingInterface_SFP (U4.6)
SFPIN.SYNCOUT_N: FPGA_ARTIX7 (U18.W22), ChassisTimingInterface_SFP (U8.2)
SFPIN.SYNCOUT_P: FPGA_ARTIX7 (U18.W21), ChassisTimingInterface_SFP (U8.3)
SQSPI.EMCLK_EN: ChassisTimingInterface3 (R195.2 Y1.1), FPGA_ARTIX7 (U18.U7)
SQSPI.PUDC_B: ChassisTimingInterface3 (R32.1 R111.1), FPGA_ARTIX7 (U18.U22)
SQSPI.QSPI_CS: ChassisTimingInterface3 (R50.2 U13.7 U16.1), FPGA_ARTIX7 (U18.T19)
SQSPI.QSPI_DQ0: ChassisTimingInterface3 (R33.2), FPGA_ARTIX7 (U18.P22)
SQSPI.QSPI_DQ1: ChassisTimingInterface3 (R61.2), FPGA_ARTIX7 (U18.R22)
SQSPI.QSPI_DQ2: ChassisTimingInterface3 (R62.2), FPGA_ARTIX7 (U18.P21)
SQSPI.QSPI_DQ3: ChassisTimingInterface3 (R63.2), FPGA_ARTIX7 (U18.R21)
SQSPI.QSPI_EMCLK: ChassisTimingInterface3 (Y1.3), FPGA_ARTIX7 (U18.V22)
SW1: ChassisTimingInterface1 (S2.16), FPGA_ARTIX7 (U18.T20)
SW2: ChassisTimingInterface1 (S2.15), FPGA_ARTIX7 (U18.P20)
SW3: ChassisTimingInterface1 (S2.14), FPGA_ARTIX7 (U18.N19)
SW4: ChassisTimingInterface1 (S2.13), FPGA_ARTIX7 (U18.N18)
SW5: ChassisTimingInterface1 (S2.12), FPGA_ARTIX7 (U18.N15)
SW6: ChassisTimingInterface1 (S2.11), FPGA_ARTIX7 (U18.N14)
SW7: ChassisTimingInterface1 (S2.10), FPGA_ARTIX7 (U18.K2)
SW8: ChassisTimingInterface1 (S2.9), FPGA_ARTIX7 (U18.J2)
SW9: ChassisTimingInterface1 (P222.6), FPGA_ARTIX7 (U18.N13)
SW10: ChassisTimingInterface1 (P222.8), FPGA_ARTIX7 (U18.L6)
T1_11.T1_N: ChassisTimingInterface1 (J3.14), FPGA_ARTIX7 (U18.V20)
T1_11.T1_P: ChassisTimingInterface1 (J3.1), FPGA_ARTIX7 (U18.U20)
T1_11.T2_N: ChassisTimingInterface1 (J3.15), FPGA_ARTIX7 (U18.L18)
T1_11.T2_P: ChassisTimingInterface1 (J3.2), FPGA_ARTIX7 (U18.M18)
T1_11.T3_N: ChassisTimingInterface1 (J3.16), FPGA_ARTIX7 (U18.R16)
T1_11.T3_P: ChassisTimingInterface1 (J3.3), FPGA_ARTIX7 (U18.P15)
T1_11.T4_N: ChassisTimingInterface1 (J3.17), FPGA_ARTIX7 (U18.L15)
T1_11.T4_P: ChassisTimingInterface1 (J3.4), FPGA_ARTIX7 (U18.L14)
T1_11.T5_N: ChassisTimingInterface1 (J3.18), FPGA_ARTIX7 (U18.R14)
T1_11.T5_P: ChassisTimingInterface1 (J3.5), FPGA_ARTIX7 (U18.P14)
T1_11.T6_N: ChassisTimingInterface1 (J3.19), FPGA_ARTIX7 (U18.Y9)
T1_11.T6_P: ChassisTimingInterface1 (J3.6), FPGA_ARTIX7 (U18.W9)
T1_11.T7_N: ChassisTimingInterface1 (J3.20), FPGA_ARTIX7 (U18.AB8)
T1_11.T7_P: ChassisTimingInterface1 (J3.7), FPGA_ARTIX7 (U18.AA8)
T1_11.T8_N: ChassisTimingInterface1 (J3.21), FPGA_ARTIX7 (U18.V8)
T1_11.T8_P: ChassisTimingInterface1 (J3.8), FPGA_ARTIX7 (U18.V9)
T1_11.T9_N: ChassisTimingInterface1 (J3.22), FPGA_ARTIX7 (U18.Y7)
T1_11.T9_P: ChassisTimingInterface1 (J3.9), FPGA_ARTIX7 (U18.Y8)
T10_N: ChassisTimingInterface1 (J3.23), FPGA_ARTIX7 (U18.AB6)
T10_P: ChassisTimingInterface1 (J3.10), FPGA_ARTIX7 (U18.AB7)
T11_N: ChassisTimingInterface1 (J3.24), FPGA_ARTIX7 (U18.W7)
T11_P: ChassisTimingInterface1 (J3.11), FPGA_ARTIX7 (U18.V7)
XADC.XADC_REF_N: ChassisTimingInterface3 (U18.L9), ChassisTimingInterface_XADC (W3.2)
XADC.XADC_REF_P: ChassisTimingInterface3 (U18.M10), ChassisTimingInterface_XADC (C174.1 R184.2 R187.2 U33.2)
XADC.XADC_V_N: ChassisTimingInterface3 (U18.M9), ChassisTimingInterface_XADC (C155.2 C188.2 R165.2)
XADC.XADC_V_P: ChassisTimingInterface3 (U18.L10), ChassisTimingInterface_XADC (C155.1 C188.1 R169.2)
XMUX0: FPGA_ARTIX7 (U18.F21), ChassisTimingInterface_XADC (U29.13)
XMUX1: FPGA_ARTIX7 (U18.M17), ChassisTimingInterface_XADC (U29.12)
XMUX2: FPGA_ARTIX7 (U18.J16), ChassisTimingInterface_XADC (U29.11)
XMUX3: FPGA_ARTIX7 (U18.F15), ChassisTimingInterface_XADC (U29.10)
XOCTRL_N: ChassisTimingInterface1 (J3.25), ChassisTimingInterface6 (R75.2)
XOCTRL_P: ChassisTimingInterface1 (J3.12), ChassisTimingInterface6 (R72.2)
